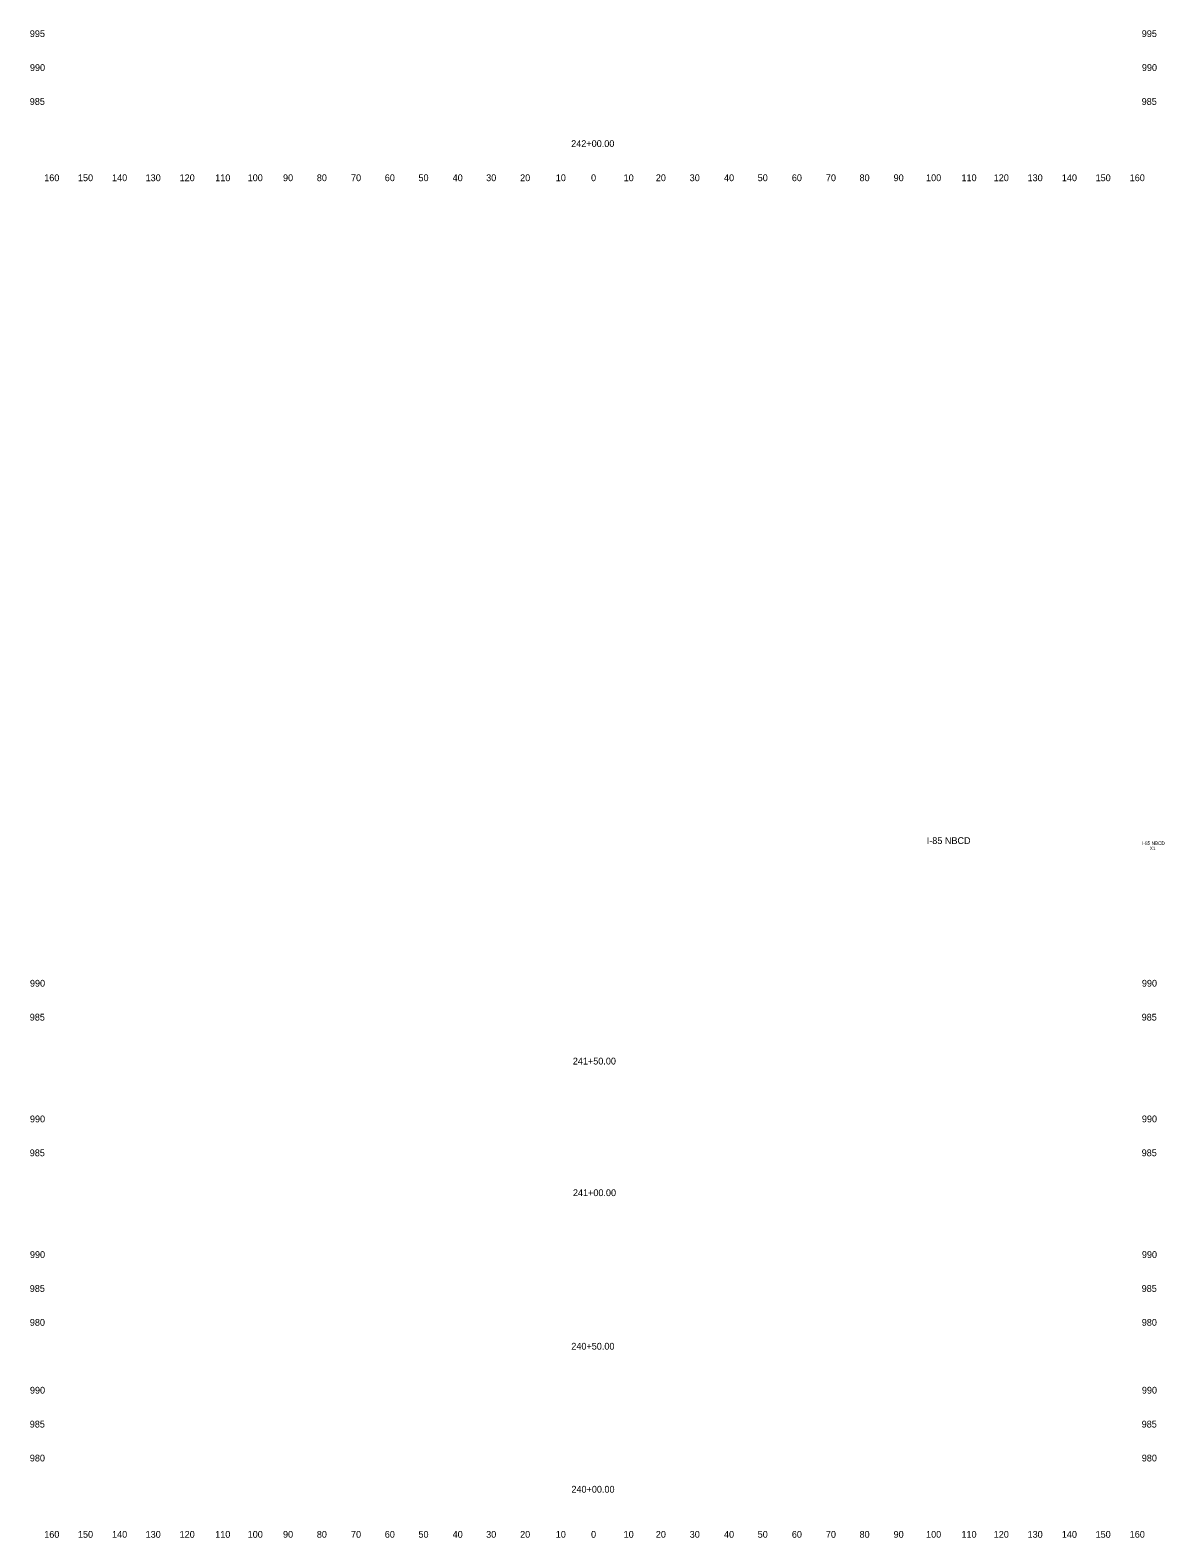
# Model space of a CAD drawing. Extents: x 4994 to 6358, y 4997 to 8804.
# Drawn here: x 4994 to 5328.2, y 4997.5 to 5442 of the extents above; entities that cross this region are included whole.
import ezdxf

# ---------------------------------------------------------------- set-up
doc = ezdxf.new("R2010")
doc.units = 0
for name, color, linetype in [('RD_SHT_ID', 7, 'Continuous'), ('RD_XS_TX_Offset', 7, 'Continuous'), ('RD_XS_TX_Station', 7, 'Continuous')]:
    doc.layers.add(name, color=color, linetype=linetype)

msp = doc.modelspace()

# ---------------------------------------------------------------- texts
at = {"layer": 'RD_SHT_ID'}
for s, height, p in [('I-85 NBCD', 2, (5258.26, 5202.06)), ('I-85 NBCD', 1, (5321.77, 5201.8)), ('X1', 1, (5324.02, 5200.3))]:
    msp.add_text(s, height=height, dxfattribs=at).set_placement(p)
at = {"layer": 'RD_XS_TX_Offset'}
for s, p in [('995', (4993.86, 5440)), ('995', (5321.66, 5440)), ('990', (4993.89, 5430)), ('990', (5321.69, 5430)), ('985', (4993.83, 5420)), ('985', (5321.63, 5420)), ('160', (4998.1, 5397.5)), ('150', (5008.04, 5397.5)), ('140', (5018.1, 5397.5)), ('130', (5027.99, 5397.5)), ('120', (5038.01, 5397.5)), ('110', (5048.51, 5397.5)), ('100', (5058.07, 5397.5)), ('90', (5068.5, 5397.5)), ('80', (5078.46, 5397.5)), ('70', (5088.54, 5397.5)), ('60', (5098.5, 5397.5)), ('50', (5108.43, 5397.5)), ('40', (5118.5, 5397.5)), ('30', (5128.39, 5397.5)), ('20', (5138.4, 5397.5)), ('10', (5148.91, 5397.5)), ('0', (5159.3, 5397.5)), ('0', (5159.3, 5397.5)), ('10', (5168.91, 5397.5)), ('20', (5178.4, 5397.5)), ('30', (5188.39, 5397.5)), ('40', (5198.5, 5397.5)), ('50', (5208.43, 5397.5)), ('60', (5218.5, 5397.5)), ('70', (5228.54, 5397.5)), ('80', (5238.46, 5397.5)), ('90', (5248.5, 5397.5)), ('100', (5258.07, 5397.5)), ('110', (5268.51, 5397.5)), ('120', (5278.01, 5397.5)), ('130', (5287.99, 5397.5)), ('140', (5298.1, 5397.5)), ('150', (5308.04, 5397.5)), ('160', (5318.1, 5397.5)), ('990', (4993.89, 5160)), ('990', (5321.69, 5160)), ('985', (4993.83, 5150)), ('985', (5321.63, 5150)), ('990', (4993.89, 5120)), ('990', (5321.69, 5120)), ('985', (4993.83, 5110)), ('985', (5321.63, 5110)), ('990', (4993.89, 5080)), ('990', (5321.69, 5080)), ('985', (4993.83, 5070)), ('985', (5321.63, 5070)), ('980', (4993.86, 5060)), ('980', (5321.66, 5060)), ('990', (4993.89, 5040)), ('990', (5321.69, 5040)), ('985', (4993.83, 5030)), ('985', (5321.63, 5030)), ('980', (4993.86, 5020)), ('980', (5321.66, 5020)), ('160', (4998.1, 4997.5)), ('150', (5008.04, 4997.5)), ('140', (5018.1, 4997.5)), ('130', (5027.99, 4997.5)), ('120', (5038.01, 4997.5)), ('110', (5048.51, 4997.5)), ('100', (5058.07, 4997.5)), ('90', (5068.5, 4997.5)), ('80', (5078.46, 4997.5)), ('70', (5088.54, 4997.5)), ('60', (5098.5, 4997.5)), ('50', (5108.43, 4997.5)), ('40', (5118.5, 4997.5)), ('30', (5128.39, 4997.5)), ('20', (5138.4, 4997.5)), ('10', (5148.91, 4997.5)), ('0', (5159.3, 4997.5)), ('0', (5159.3, 4997.5)), ('10', (5168.91, 4997.5)), ('20', (5178.4, 4997.5)), ('30', (5188.39, 4997.5)), ('40', (5198.5, 4997.5)), ('50', (5208.43, 4997.5)), ('60', (5218.5, 4997.5)), ('70', (5228.54, 4997.5)), ('80', (5238.46, 4997.5)), ('90', (5248.5, 4997.5)), ('100', (5258.07, 4997.5)), ('110', (5268.51, 4997.5)), ('120', (5278.01, 4997.5)), ('130', (5287.99, 4997.5)), ('140', (5298.1, 4997.5)), ('150', (5308.04, 4997.5)), ('160', (5318.1, 4997.5))]:
    msp.add_text(s, height=2, dxfattribs=at).set_placement(p)
at = {"layer": 'RD_XS_TX_Station'}
for s, p in [('242+00.00', (5153.46, 5407.58)), ('241+50.00', (5153.93, 5137.04)), ('241+00.00', (5153.96, 5098.23)), ('240+50.00', (5153.49, 5052.97)), ('240+00.00', (5153.52, 5010.8))]:
    msp.add_text(s, height=2, dxfattribs=at).set_placement(p)

doc.saveas('drawing.dxf')
